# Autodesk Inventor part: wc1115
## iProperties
Shininess: 64.0
Length Units: 11272
Angle Units: 11279
Time Units: 11290
Mass Units: 11286
Length Display Precision: 3
Angle Display Precision: 2
Compacted: True
Part Number: wc1115
Document SubType Name: Modeling
Created: 2004-08
Designer: John Blackburn
Manufacturer: Standard
Standards Organization: Custom
Density: 0.0
Volumn: 0.0
Area: 0.0
PropertySet Name: Model Information
Control State: 0
Master: False
Checked Out: False
Author: John Blackburn
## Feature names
1. Base1
